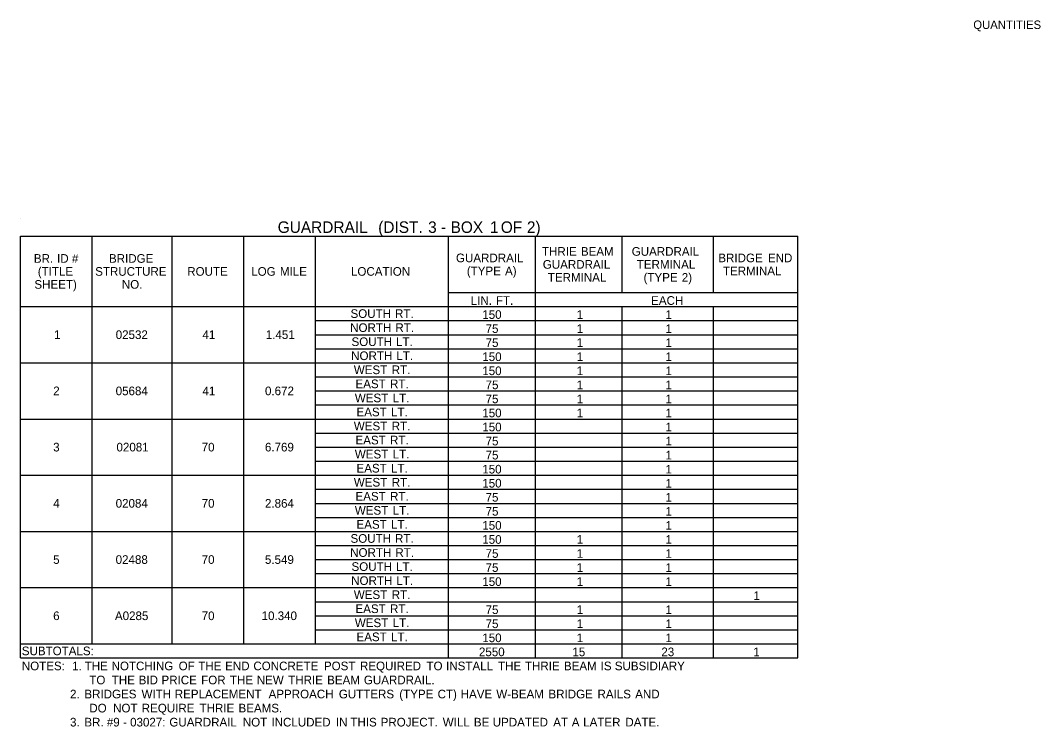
# Model space of a CAD drawing. Extents: x 544478 to 1930787, y -1948294 to 596640.
# Drawn here: x 546902 to 547610, y -1946546 to -1946056 of the extents above; entities that cross this region are included whole.
import ezdxf

# ---------------------------------------------------------------- set-up
doc = ezdxf.new("R2010")
doc.units = 0
doc.layers.add('Default', color=7, linetype='Continuous')
doc.layers.add('R_Border Prem', color=7, linetype='Continuous')

msp = doc.modelspace()

# ---------------------------------------------------------------- linework, layer by layer
at = {"layer": 'Default'}
for p, q in [((546902.33, -1946193.54), (546902.33, -1946193.54)), ((546902.33, -1946206.22), (547441.51, -1946206.22)), ((546902.33, -1946498.72), (546902.33, -1946206.22)), ((546952.06, -1946488.97), (546952.06, -1946206.22)), ((547007.63, -1946488.97), (547007.63, -1946206.22)), ((547057.36, -1946488.97), (547057.36, -1946206.22)), ((547107.08, -1946488.97), (547107.08, -1946206.22)), ((547199.22, -1946498.72), (547199.22, -1946206.22)), ((547259.67, -1946498.72), (547259.67, -1946206.22)), ((547319.63, -1946245.22), (547319.63, -1946206.22)), ((547383.01, -1946245.22), (547383.01, -1946206.22)), ((547441.51, -1946332.97), (547441.51, -1946206.22)), ((547199.22, -1946245.22), (547441.51, -1946245.22)), ((547259.67, -1946498.72), (547259.67, -1946245.22)), ((546902.33, -1946254.97), (547441.51, -1946254.97)), ((547319.63, -1946498.72), (547319.63, -1946254.97)), ((547319.63, -1946498.72), (547319.63, -1946254.97)), ((547383.01, -1946498.72), (547383.01, -1946254.97)), ((547383.01, -1946498.72), (547383.01, -1946254.97)), ((547107.08, -1946264.72), (547441.51, -1946264.72)), ((547107.08, -1946274.47), (547199.22, -1946274.47)), ((547107.08, -1946274.47), (547441.51, -1946274.47)), ((547107.08, -1946284.22), (547441.51, -1946284.22)), ((546902.33, -1946293.97), (547441.51, -1946293.97)), ((547107.08, -1946293.97), (547199.22, -1946293.97)), ((547199.22, -1946293.97), (547441.51, -1946293.97)), ((547107.08, -1946303.72), (547441.51, -1946303.72)), ((547107.08, -1946313.47), (547199.22, -1946313.47)), ((547107.08, -1946313.47), (547441.51, -1946313.47)), ((547107.08, -1946323.22), (547441.51, -1946323.22)), ((546902.33, -1946332.97), (547441.51, -1946332.97)), ((547107.08, -1946332.97), (547199.22, -1946332.97)), ((547199.22, -1946332.97), (547441.51, -1946332.97)), ((547441.51, -1946488.97), (547441.51, -1946332.97)), ((547107.08, -1946342.72), (547441.51, -1946342.72)), ((547107.08, -1946352.47), (547199.22, -1946352.47)), ((547107.08, -1946352.47), (547441.51, -1946352.47)), ((547107.08, -1946362.22), (547441.51, -1946362.22)), ((546902.33, -1946371.97), (547441.51, -1946371.97)), ((547107.08, -1946371.97), (547441.51, -1946371.97)), ((547107.08, -1946381.72), (547441.51, -1946381.72)), ((547107.08, -1946391.47), (547199.22, -1946391.47)), ((547107.08, -1946391.47), (547441.51, -1946391.47)), ((547107.08, -1946401.22), (547441.51, -1946401.22)), ((546902.33, -1946410.97), (547441.51, -1946410.97)), ((547107.08, -1946410.97), (547199.22, -1946410.97)), ((547199.22, -1946410.97), (547383.01, -1946410.97)), ((547383.01, -1946410.97), (547441.51, -1946410.97)), ((547107.08, -1946420.72), (547441.51, -1946420.72)), ((547107.08, -1946430.47), (547199.22, -1946430.47)), ((547107.08, -1946430.47), (547441.51, -1946430.47)), ((547107.08, -1946440.22), (547441.51, -1946440.22)), ((546902.33, -1946449.97), (547441.51, -1946449.97)), ((547107.08, -1946449.97), (547441.51, -1946449.97)), ((547107.08, -1946459.72), (547441.51, -1946459.72)), ((547107.08, -1946469.47), (547199.22, -1946469.47)), ((547107.08, -1946469.47), (547441.51, -1946469.47)), ((547107.08, -1946479.22), (547441.51, -1946479.22)), ((546902.33, -1946488.97), (547441.51, -1946488.97)), ((547107.08, -1946488.97), (547441.51, -1946488.97)), ((547441.51, -1946498.72), (547441.51, -1946488.97)), ((546902.33, -1946498.72), (547441.51, -1946498.72))]:
    msp.add_line(p, q, dxfattribs=at)

# ---------------------------------------------------------------- texts
for s, height, p in [('GUARDRAIL', 8, (547080.76, -1946203.88)), (' (DIST.', 8, (547147.49, -1946203.88)), (' 3', 8, (547182.11, -1946203.88)), (' -', 8, (547190.95, -1946203.88)), (' BOX', 8, (547197.69, -1946203.88)), (' 1', 8, (547225.01, -1946203.88)), (' OF', 8, (547232.51, -1946203.88)), (' 2)', 8, (547250.62, -1946203.88)), ('THRIE', 6, (547264.07, -1946219.72)), (' BEAM', 6, (547288.81, -1946219.72)), ('GUARDRAIL', 6, (547326.29, -1946219.72)), ('BR.', 6, (546911.67, -1946224.59)), (' ID', 6, (546925.53, -1946224.59)), (' #', 6, (546935.83, -1946224.59)), ('BRIDGE', 6, (546963.75, -1946224.59)), ('GUARDRAIL', 6, (547204.42, -1946224.22)), ('GUARDRAIL', 6, (547264.63, -1946228.72)), ('TERMINAL', 6, (547329.79, -1946228.72)), ('BRIDGE', 6, (547386.35, -1946224.22)), (' END', 6, (547418.54, -1946224.22)), ('(TITLE', 6, (546914.36, -1946233.59)), ('STRUCTURE', 6, (546954.2, -1946233.59)), ('ROUTE', 6, (547018.03, -1946233.59)), ('LOG', 6, (547062.42, -1946233.59)), (' MILE', 6, (547080.08, -1946233.59)), ('LOCATION', 6, (547131.6, -1946233.59)), ('(TYPE', 6, (547211.94, -1946233.22)), (' A)', 6, (547236.21, -1946233.22)), ('TERMINAL', 6, (547389.56, -1946233.22)), ('SHEET)', 6, (546912.04, -1946242.59)), ('NO.', 6, (546972.68, -1946242.59)), ('TERMINAL', 6, (547268.12, -1946237.72)), ('(TYPE', 6, (547334.51, -1946237.72)), (' 2)', 6, (547358.78, -1946237.72)), ('LIN.', 6, (547214.65, -1946253.77)), (' FT.', 6, (547229.91, -1946253.77)), ('EACH', 6, (547339.76, -1946253.77)), ('SOUTH', 6, (547131.27, -1946262.84)), (' RT.', 6, (547159.93, -1946262.84)), ('150', 6, (547222.66, -1946263.52)), ('1', 6, (547288.09, -1946263.52)), ('1', 6, (547349.76, -1946263.52)), ('1', 6, (546925.63, -1946277.47)), ('02532', 6, (546968.42, -1946277.47)), ('41', 6, (547028.6, -1946277.47)), ('1.451', 6, (547072.51, -1946277.47)), ('NORTH', 6, (547131.03, -1946272.59)), (' RT.', 6, (547160.17, -1946272.59)), ('75', 6, (547224.95, -1946273.27)), ('1', 6, (547288.09, -1946273.27)), ('1', 6, (547349.76, -1946273.27)), ('SOUTH', 6, (547131.96, -1946282.34)), (' LT.', 6, (547160.63, -1946282.34)), ('75', 6, (547224.95, -1946283.02)), ('1', 6, (547288.09, -1946283.02)), ('1', 6, (547349.76, -1946283.02)), ('NORTH', 6, (547131.73, -1946292.09)), (' LT.', 6, (547160.86, -1946292.09)), ('150', 6, (547222.66, -1946292.77)), ('1', 6, (547288.09, -1946292.77)), ('1', 6, (547349.76, -1946292.77)), ('WEST', 6, (547133.57, -1946301.84)), (' RT.', 6, (547157.63, -1946301.84)), ('150', 6, (547222.66, -1946302.52)), ('1', 6, (547288.09, -1946302.52)), ('1', 6, (547349.76, -1946302.52)), ('EAST', 6, (547134.73, -1946311.59)), (' RT.', 6, (547156.47, -1946311.59)), ('75', 6, (547224.95, -1946312.27)), ('1', 6, (547288.09, -1946312.27)), ('1', 6, (547349.76, -1946312.27)), ('2', 6, (546925.09, -1946316.47)), ('05684', 6, (546968.4, -1946316.47)), ('41', 6, (547028.6, -1946316.47)), ('0.672', 6, (547071.96, -1946316.47)), ('WEST', 6, (547134.27, -1946321.34)), (' LT.', 6, (547158.32, -1946321.34)), ('75', 6, (547224.95, -1946322.02)), ('1', 6, (547288.09, -1946322.02)), ('1', 6, (547349.76, -1946322.02)), ('EAST', 6, (547135.43, -1946331.09)), (' LT.', 6, (547157.16, -1946331.09)), ('150', 6, (547222.66, -1946331.77)), ('1', 6, (547288.09, -1946331.77)), ('1', 6, (547349.76, -1946331.77)), ('WEST', 6, (547133.57, -1946340.84)), (' RT.', 6, (547157.63, -1946340.84)), ('150', 6, (547222.66, -1946341.52)), ('1', 6, (547349.76, -1946341.52)), ('3', 6, (546925.05, -1946355.47)), ('02081', 6, (546968.96, -1946355.47)), ('70', 6, (547028.04, -1946355.47)), ('6.769', 6, (547071.92, -1946355.47)), ('EAST', 6, (547134.73, -1946350.59)), (' RT.', 6, (547156.47, -1946350.59)), ('75', 6, (547224.95, -1946351.27)), ('1', 6, (547349.76, -1946351.27)), ('WEST', 6, (547134.27, -1946360.34)), (' LT.', 6, (547158.32, -1946360.34)), ('75', 6, (547224.95, -1946361.02)), ('1', 6, (547349.76, -1946361.02)), ('EAST', 6, (547135.43, -1946370.09)), (' LT.', 6, (547157.16, -1946370.09)), ('150', 6, (547222.66, -1946370.77)), ('1', 6, (547349.76, -1946370.77)), ('WEST', 6, (547133.57, -1946379.84)), (' RT.', 6, (547157.63, -1946379.84)), ('150', 6, (547222.66, -1946380.52)), ('1', 6, (547349.76, -1946380.52)), ('EAST', 6, (547134.73, -1946389.59)), (' RT.', 6, (547156.47, -1946389.59)), ('75', 6, (547224.95, -1946390.27)), ('1', 6, (547349.76, -1946390.27)), ('4', 6, (546925.07, -1946394.47)), ('02084', 6, (546968.4, -1946394.47)), ('70', 6, (547028.04, -1946394.47)), ('2.864', 6, (547071.94, -1946394.47)), ('WEST', 6, (547134.27, -1946399.34)), (' LT.', 6, (547158.32, -1946399.34)), ('75', 6, (547224.95, -1946400.02)), ('1', 6, (547349.76, -1946400.02)), ('EAST', 6, (547135.43, -1946409.09)), (' LT.', 6, (547157.16, -1946409.09)), ('150', 6, (547222.66, -1946409.77)), ('1', 6, (547349.76, -1946409.77)), ('SOUTH', 6, (547131.27, -1946418.84)), (' RT.', 6, (547159.93, -1946418.84)), ('150', 6, (547222.66, -1946419.52)), ('1', 6, (547288.09, -1946419.52)), ('1', 6, (547349.76, -1946419.52)), ('5', 6, (546925.03, -1946433.47)), ('02488', 6, (546968.38, -1946433.47)), ('70', 6, (547028.04, -1946433.47)), ('5.549', 6, (547071.92, -1946433.47)), ('NORTH', 6, (547131.03, -1946428.59)), (' RT.', 6, (547160.17, -1946428.59)), ('75', 6, (547224.95, -1946429.27)), ('1', 6, (547288.09, -1946429.27)), ('1', 6, (547349.76, -1946429.27)), ('SOUTH', 6, (547131.96, -1946438.34)), (' LT.', 6, (547160.63, -1946438.34)), ('75', 6, (547224.95, -1946439.02)), ('1', 6, (547288.09, -1946439.02)), ('1', 6, (547349.76, -1946439.02)), ('NORTH', 6, (547131.73, -1946448.09)), (' LT.', 6, (547160.86, -1946448.09)), ('150', 6, (547222.66, -1946448.77)), ('1', 6, (547288.09, -1946448.77)), ('1', 6, (547349.76, -1946448.77)), ('WEST', 6, (547133.57, -1946457.84)), (' RT.', 6, (547157.63, -1946457.84)), ('1', 6, (547410.7, -1946458.52)), ('EAST', 6, (547134.73, -1946467.59)), (' RT.', 6, (547156.47, -1946467.59)), ('75', 6, (547224.95, -1946468.27)), ('1', 6, (547288.09, -1946468.27)), ('1', 6, (547349.76, -1946468.27)), ('6', 6, (546925.05, -1946472.47)), ('A0285', 6, (546967.89, -1946472.47)), ('70', 6, (547028.04, -1946472.47)), ('10.340', 6, (547069.61, -1946472.47)), ('WEST', 6, (547134.27, -1946477.34)), (' LT.', 6, (547158.32, -1946477.34)), ('75', 6, (547224.95, -1946478.02)), ('1', 6, (547288.09, -1946478.02)), ('1', 6, (547349.76, -1946478.02)), ('EAST', 6, (547135.43, -1946487.09)), (' LT.', 6, (547157.16, -1946487.09)), ('150', 6, (547222.66, -1946487.77)), ('1', 6, (547288.09, -1946487.77)), ('1', 6, (547349.76, -1946487.77)), ('SUBTOTALS:', 6, (546903.31, -1946496.84)), ('2550', 6, (547220.33, -1946497.52)), ('15', 6, (547285.12, -1946497.52)), ('23', 6, (547346.84, -1946497.52)), ('1', 6, (547410.61, -1946497.52)), ('NOTES:', 6, (546903.31, -1946507.27)), ('  1.', 6, (546933.79, -1946507.27)), (' THE', 6, (546944.7, -1946507.27)), (' NOTCHING', 6, (546963.35, -1946507.27)), (' OF', 6, (547009.86, -1946507.27)), (' THE', 6, (547023.45, -1946507.27)), (' END', 6, (547042.1, -1946507.27)), (' CONCRETE', 6, (547061.68, -1946507.27)), (' POST', 6, (547110.61, -1946507.27)), (' REQUIRED', 6, (547135.6, -1946507.27)), (' TO', 6, (547181.73, -1946507.27)), (' INSTALL', 6, (547195.33, -1946507.27)), (' THE', 6, (547231.37, -1946507.27)), (' THRIE', 6, (547250.02, -1946507.27)), (' BEAM', 6, (547277.05, -1946507.27)), (' IS', 6, (547302.51, -1946507.27)), (' SUBSIDIARY', 6, (547312.32, -1946507.27)), ('                     TO', 6, (546903.31, -1946517.02)), (' THE', 6, (546963.46, -1946517.02)), (' BID', 6, (546982.11, -1946517.02)), (' PRICE', 6, (546997.96, -1946517.02)), (' FOR', 6, (547025.47, -1946517.02)), (' THE', 6, (547045.38, -1946517.02)), (' NEW', 6, (547064.03, -1946517.02)), (' THRIE', 6, (547085.82, -1946517.02)), (' BEAM', 6, (547112.85, -1946517.02)), (' GUARDRAIL.', 6, (547138.31, -1946517.02)), ('               2.', 6, (546903.31, -1946526.77)), (' BRIDGES', 6, (546944.48, -1946526.77)), (' WITH', 6, (546984.11, -1946526.77)), (' REPLACEMENT', 6, (547007.17, -1946526.77)), (' APPROACH', 6, (547072.23, -1946526.77)), (' GUTTERS', 6, (547120.93, -1946526.77)), (' (TYPE', 6, (547162.88, -1946526.77)), (' CT)', 6, (547189.45, -1946526.77)), (' HAVE', 6, (547205.45, -1946526.77)), (' W-BEAM', 6, (547230.16, -1946526.77)), (' BRIDGE', 6, (547266.32, -1946526.77)), (' RAILS', 6, (547300.34, -1946526.77)), (' AND', 6, (547326.46, -1946526.77)), ('                     DO', 6, (546903.31, -1946536.52)), (' NOT', 6, (546964.39, -1946536.52)), (' REQUIRE', 6, (546984.25, -1946536.52)), (' THRIE', 6, (547024.33, -1946536.52)), (' BEAMS.', 6, (547051.36, -1946536.52)), ('               3.', 6, (546903.31, -1946546.27)), (' BR.', 6, (546944.48, -1946546.27)), (' #9', 6, (546960.05, -1946546.27)), (' 03027:', 6, (546976.18, -1946546.27)), (' GUARDRAIL', 6, (547003.41, -1946546.27)), (' NOT', 6, (547054.35, -1946546.27)), (' INCLUDED', 6, (547074.21, -1946546.27)), (' IN', 6, (547118.95, -1946546.27)), (' THIS', 6, (547128.97, -1946546.27)), (' PROJECT.', 6, (547149.96, -1946546.27)), (' WILL', 6, (547193.01, -1946546.27)), (' BE', 6, (547214.6, -1946546.27)), (' UPDATED', 6, (547227.67, -1946546.27)), (' AT', 6, (547269.61, -1946546.27)), (' A', 6, (547282.49, -1946546.27)), (' LATER', 6, (547290.42, -1946546.27)), (' DATE.', 6, (547319.66, -1946546.27)), (' -', 6, (546971.33, -1946546.27))]:
    msp.add_text(s, height=height, dxfattribs=at).set_placement(p)
at = {"layer": 'R_Border Prem'}
msp.add_text('QUANTITIES', height=5.862, rotation=360, dxfattribs=at).set_placement((547563.18, -1946062.39))

doc.saveas('drawing.dxf')
